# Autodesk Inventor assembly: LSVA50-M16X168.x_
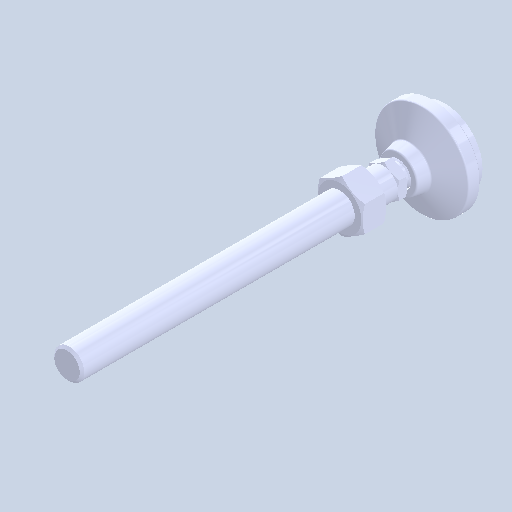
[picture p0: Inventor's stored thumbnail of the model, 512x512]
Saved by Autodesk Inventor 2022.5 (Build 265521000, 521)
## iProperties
Created: 2024-08
Part Number: LSVA50-M16X168.x_
Document SubType Name: Assembly
Designer: ImaoCorp
Author: ImaoCorp
Sending System: SOLIDWORKS 2022-2022290
MC: AMD64
MC_MODEL: Intel64 Family 6 Model 60 Stepping 3, GenuineIntel
OS: Windows_NT
FRU: Parasolid Version 33.1, build 260,  4-25-2022
FORMAT: text
GUISE: transmit
KEY: FILELSVA50-M16X168.x_t
DATE: Fri Aug 23 16:08:40 2024
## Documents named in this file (4)
- X:\14_SW2022-Inv2022\06_2024-10新製品(SME)\ELS_データ\l\lsva50-m16x168\LSVA50-M16X168.x_.iam
- X:\14_SW2022-Inv2022\06_2024-10新製品(SME)\ELS_データ\l\lsva50-m16x168\LSVA50-M16X168_01.ipt
- X:\14_SW2022-Inv2022\06_2024-10新製品(SME)\ELS_データ\l\lsva50-m16x168\LSVA50-M16X168_02.ipt
- X:\14_SW2022-Inv2022\06_2024-10新製品(SME)\ELS_データ\l\lsva50-m16x168\LSVA50-M16X168_03.ipt
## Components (3 placed, 3 different names)
1. LSVA50-M16X168_01
2. LSVA50-M16X168_02
3. LSVA50-M16X168_03
